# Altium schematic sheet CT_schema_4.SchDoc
size 316 x 185 mm
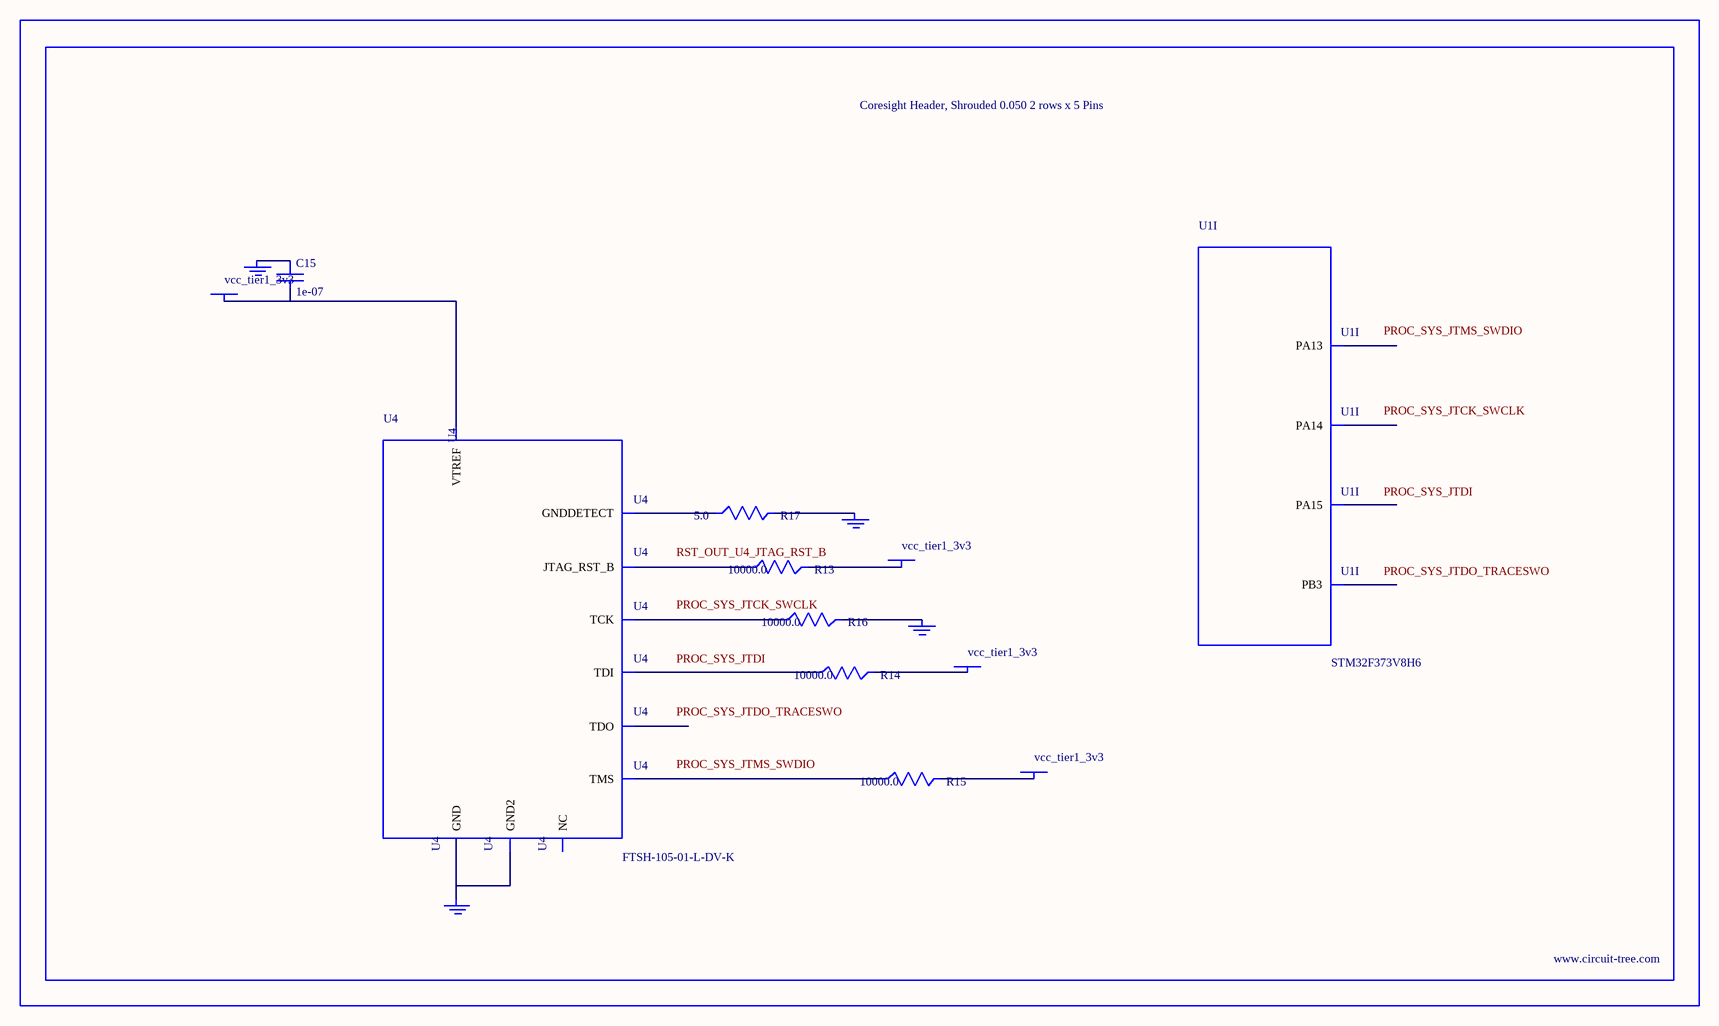
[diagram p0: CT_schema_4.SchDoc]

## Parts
BORDER3  (no value)
C15  1e-07  [C0402]
GND_INSTANCE_3_0  (no value)
GND_INSTANCE_3_1  (no value)
GND_INSTANCE_3_2  (no value)
GND_INSTANCE_3_3  (no value)
POWER_INSTANCE_3_0  vcc_tier1_3v3
POWER_INSTANCE_3_1  vcc_tier1_3v3
POWER_INSTANCE_3_2  vcc_tier1_3v3
POWER_INSTANCE_3_3  vcc_tier1_3v3
R13  10000.0  [R0603]
R14  10000.0  [R0603]
R15  10000.0  [R0603]
R16  10000.0  [R0603]
R17  5.0  [R0603]
U1  STM32F373V8H6  [UFBGA100]  (part I of 9)
U4  FTSH-105-01-L-DV-K  [SAMTEC_FTSH-105-01-L-DV-K]

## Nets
NetC15_1: C15.1 GND_INSTANCE_3_0.0(GND)
NetC15_2: C15.2 POWER_INSTANCE_3_0.0(PWR) U4.1(VTREF)
NetGND_INSTANCE_3_1_0: GND_INSTANCE_3_1.0(GND) R16.2
NetGND_INSTANCE_3_2_0: GND_INSTANCE_3_2.0(GND) R17.2
NetGND_INSTANCE_3_3_0: GND_INSTANCE_3_3.0(GND) U4.3(GND) U4.5(GND2)
NetPOWER_INSTANCE_3_1_0: POWER_INSTANCE_3_1.0(PWR) R15.2
NetPOWER_INSTANCE_3_2_0: POWER_INSTANCE_3_2.0(PWR) R14.2
NetPOWER_INSTANCE_3_3_0: POWER_INSTANCE_3_3.0(PWR) R13.2
NetR13_1: R13.1 U4.10(JTAG_RST_B)
NetR14_1: R14.1 U4.8(TDI)
NetR15_1: R15.1 U4.2(TMS)
NetR16_1: R16.1 U4.4(TCK)
NetR17_1: R17.1 U4.9(GNDDETECT)

Not connected (* = marked no-connect by the designer): U1 A8(PB3) A9(PA15) A10(PA14) A11(PA13); U4 6(TDO) 7(NC)

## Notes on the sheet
- Labels drawn without touching a wire or pin: PROC_SYS_JTCK_SWCLK, PROC_SYS_JTDI, PROC_SYS_JTDO_TRACESWO, PROC_SYS_JTMS_SWDIO, RST_OUT_U4_JTAG_RST_B

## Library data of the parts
BORDER3 = BORDER_PAGE3
C15 = C0402C104K3RACTU
GND_INSTANCE_3_0-GND_INSTANCE_3_3 = GND
POWER_INSTANCE_3_0-POWER_INSTANCE_3_3 = PWR
R13-R16 = RC0603JR-0710KL
R17 = ERJ-3GEYJ5R1V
